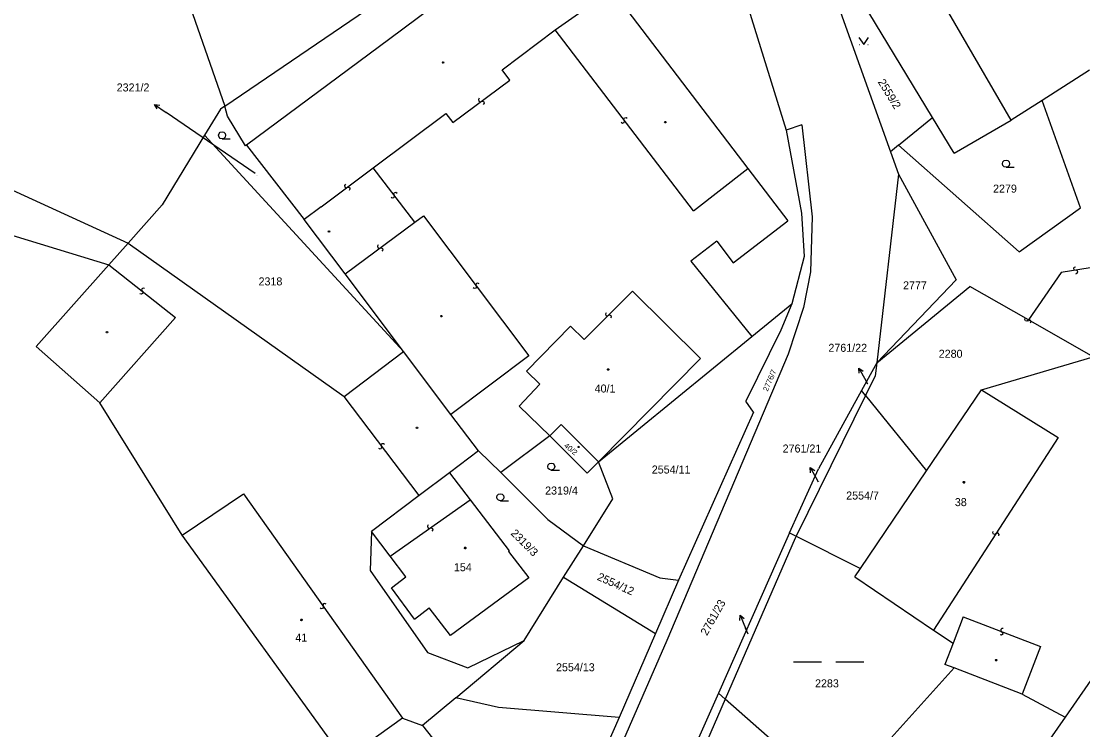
# Model space of a CAD drawing. Extents: x -747792 to -745414, y -1093712 to -1091463.
# Drawn here: x -746685.5 to -746572.8, y -1092966.2 to -1092891 of the extents above; entities that cross this region are included whole.
import ezdxf

# ---------------------------------------------------------------- set-up
doc = ezdxf.new("R2010")
doc.units = 0
for name, color, linetype in [('Pracovní_bod JDTM STC_VC', 7, 'Continuous'), ('Pracovní_bod JDTM STC_VC - výška', 7, 'Continuous'), ('Pracovní_bod JDTM STC_VC - číslo', 7, 'Continuous'), ('Pracovní_bod NN - výška', 7, 'Continuous'), ('Pracovní_bod polohopisu', 7, 'Continuous'), ('Pracovní_bod polohopisu - výška', 7, 'Continuous')]:
    doc.layers.add(name, color=color, linetype=linetype)

msp = doc.modelspace()

# ---------------------------------------------------------------- linework, layer by layer
at = {"layer": 'Pracovní_bod JDTM STC_VC - výška'}
for points in [[(-746640.68, -1092895.33), (-746640.63, -1092895.41), (-746640.68, -1092895.48), (-746640.76, -1092895.48), (-746640.81, -1092895.41), (-746640.76, -1092895.33)], [(-746617.05, -1092901.66), (-746617.01, -1092901.73), (-746617.05, -1092901.8), (-746617.15, -1092901.8), (-746617.19, -1092901.73), (-746617.15, -1092901.66)], [(-746652.79, -1092913.25), (-746652.75, -1092913.32), (-746652.79, -1092913.4), (-746652.89, -1092913.4), (-746652.93, -1092913.32), (-746652.89, -1092913.25)], [(-746640.84, -1092922.25), (-746640.8, -1092922.32), (-746640.84, -1092922.4), (-746640.94, -1092922.4), (-746640.98, -1092922.32), (-746640.94, -1092922.25)], [(-746676.38, -1092923.97), (-746676.33, -1092924.04), (-746676.38, -1092924.11), (-746676.47, -1092924.11), (-746676.51, -1092924.04), (-746676.47, -1092923.97)], [(-746623.19, -1092927.91), (-746623.14, -1092927.92), (-746623.11, -1092927.96), (-746623.1, -1092927.99), (-746623.11, -1092928.04), (-746623.16, -1092928.07), (-746623.19, -1092928.07), (-746623.23, -1092928.06), (-746623.26, -1092928.03), (-746623.27, -1092927.99), (-746623.26, -1092927.94), (-746623.22, -1092927.91)], [(-746643.45, -1092934.1), (-746643.4, -1092934.18), (-746643.45, -1092934.26), (-746643.53, -1092934.26), (-746643.58, -1092934.18), (-746643.53, -1092934.1)], [(-746626.33, -1092936.14), (-746626.3, -1092936.15), (-746626.28, -1092936.18), (-746626.27, -1092936.2), (-746626.28, -1092936.23), (-746626.31, -1092936.25), (-746626.33, -1092936.26), (-746626.36, -1092936.25), (-746626.38, -1092936.23), (-746626.39, -1092936.2), (-746626.38, -1092936.17), (-746626.35, -1092936.15)], [(-746585.4, -1092939.88), (-746585.35, -1092939.89), (-746585.33, -1092939.93), (-746585.32, -1092939.96), (-746585.33, -1092940.01), (-746585.36, -1092940.04), (-746585.4, -1092940.04), (-746585.45, -1092940.03), (-746585.48, -1092940), (-746585.49, -1092939.96), (-746585.48, -1092939.92), (-746585.44, -1092939.88)], [(-746638.38, -1092946.84), (-746638.33, -1092946.85), (-746638.3, -1092946.9), (-746638.29, -1092946.93), (-746638.3, -1092946.98), (-746638.34, -1092947.01), (-746638.38, -1092947.02), (-746638.43, -1092947), (-746638.46, -1092946.97), (-746638.47, -1092946.93), (-746638.46, -1092946.88), (-746638.42, -1092946.85)], [(-746655.77, -1092954.48), (-746655.72, -1092954.49), (-746655.7, -1092954.53), (-746655.69, -1092954.56), (-746655.7, -1092954.6), (-746655.74, -1092954.64), (-746655.77, -1092954.65), (-746655.82, -1092954.63), (-746655.84, -1092954.6), (-746655.85, -1092954.56), (-746655.84, -1092954.52), (-746655.8, -1092954.48)], [(-746581.93, -1092958.78), (-746581.88, -1092958.85), (-746581.93, -1092958.93), (-746582.01, -1092958.93), (-746582.06, -1092958.85), (-746582.01, -1092958.78)]]:
    msp.add_lwpolyline(points, close=True, dxfattribs=at)
at = {"layer": 'Pracovní_bod JDTM STC_VC - číslo'}
for points in [[(-746596.54, -1092892.73), (-746596.04, -1092893.48), (-746595.54, -1092892.73)], [(-746596.52, -1092893.48), (-746596.47, -1092893.48)], [(-746595.61, -1092893.48), (-746595.57, -1092893.48)], [(-746664.2, -1092903.5), (-746664.39, -1092903.45), (-746664.52, -1092903.31), (-746664.58, -1092903.12), (-746664.52, -1092902.94), (-746664.39, -1092902.8), (-746664.2, -1092902.75), (-746664.01, -1092902.8), (-746663.88, -1092902.94), (-746663.83, -1092903.12), (-746663.88, -1092903.31), (-746664.01, -1092903.45), (-746664.2, -1092903.5), (-746663.33, -1092903.5)], [(-746580.92, -1092906.51), (-746581.11, -1092906.46), (-746581.25, -1092906.32), (-746581.3, -1092906.14), (-746581.25, -1092905.95), (-746581.11, -1092905.81), (-746580.92, -1092905.76), (-746580.73, -1092905.81), (-746580.59, -1092905.95), (-746580.55, -1092906.14), (-746580.59, -1092906.32), (-746580.73, -1092906.46), (-746580.92, -1092906.51), (-746580.05, -1092906.51)], [(-746629.23, -1092938.67), (-746629.42, -1092938.62), (-746629.55, -1092938.48), (-746629.6, -1092938.29), (-746629.55, -1092938.11), (-746629.42, -1092937.97), (-746629.23, -1092937.92), (-746629.04, -1092937.97), (-746628.91, -1092938.11), (-746628.85, -1092938.29), (-746628.91, -1092938.48), (-746629.04, -1092938.62), (-746629.23, -1092938.67), (-746628.35, -1092938.67)], [(-746634.63, -1092941.92), (-746634.82, -1092941.87), (-746634.96, -1092941.73), (-746635.01, -1092941.54), (-746634.96, -1092941.36), (-746634.82, -1092941.22), (-746634.63, -1092941.17), (-746634.44, -1092941.22), (-746634.3, -1092941.36), (-746634.26, -1092941.54), (-746634.3, -1092941.73), (-746634.44, -1092941.87), (-746634.63, -1092941.92), (-746633.76, -1092941.92)], [(-746603.51, -1092959.03), (-746600.51, -1092959.03)], [(-746599.01, -1092959.03), (-746596.01, -1092959.03)]]:
    msp.add_lwpolyline(points, dxfattribs=at)
at = {"layer": 'Pracovní_bod NN - výška'}
for points in [[(-746663.9, -1092900.02), (-746615.33, -1092867)], [(-746615.33, -1092867), (-746604.26, -1092902.58)], [(-746673.9, -1092871.4), (-746663.9, -1092900.02)], [(-746605.01, -1092871.84), (-746593.18, -1092904.87)], [(-746628.81, -1092879.8), (-746646.38, -1092892.9)], [(-746588.72, -1092901.23), (-746599.54, -1092883.4)], [(-746622.81, -1092887.67), (-746608.35, -1092906.65)], [(-746646.38, -1092892.9), (-746661.6, -1092904.16)], [(-746572.05, -1092896.22), (-746577.08, -1092899.42)], [(-746577.08, -1092899.42), (-746580.37, -1092901.51)], [(-746573.02, -1092910.82), (-746577.08, -1092899.42)], [(-746664.37, -1092900.34), (-746666.05, -1092903.11)], [(-746663.9, -1092900.02), (-746664.37, -1092900.34)], [(-746663.62, -1092901.08), (-746663.9, -1092900.02)], [(-746661.72, -1092904.25), (-746663.62, -1092901.08)], [(-746602.61, -1092902.03), (-746604.26, -1092902.58)], [(-746602.61, -1092902.03), (-746601.52, -1092911.78)], [(-746592.33, -1092904.17), (-746588.72, -1092901.23)], [(-746586.43, -1092905.01), (-746588.72, -1092901.23)], [(-746586.43, -1092905.01), (-746580.37, -1092901.51)], [(-746699.3, -1092903.07), (-746674.17, -1092914.57)], [(-746666.05, -1092903.11), (-746670.57, -1092910.51)], [(-746666.05, -1092903.11), (-746644.92, -1092926.07)], [(-746604.26, -1092902.58), (-746602.64, -1092911.38)], [(-746661.6, -1092904.16), (-746661.72, -1092904.25)], [(-746661.6, -1092904.16), (-746655.46, -1092912.05)], [(-746592.33, -1092904.17), (-746593.18, -1092904.87)], [(-746592.33, -1092904.17), (-746579.52, -1092915.49)], [(-746593.18, -1092904.87), (-746592.33, -1092907.24)], [(-746608.35, -1092906.65), (-746604.1, -1092912.22)], [(-746592.33, -1092907.24), (-746594.65, -1092927.27)], [(-746592.33, -1092907.24), (-746586.23, -1092918.47)], [(-746701.96, -1092909.01), (-746676.22, -1092916.88)], [(-746674.17, -1092914.57), (-746670.57, -1092910.51)], [(-746579.52, -1092915.49), (-746573.02, -1092910.82)], [(-746651.11, -1092917.83), (-746655.46, -1092912.05)], [(-746602.64, -1092911.38), (-746602.35, -1092915.98)], [(-746601.52, -1092911.78), (-746601.7, -1092917.63)], [(-746609.89, -1092916.66), (-746604.1, -1092912.22)], [(-746611.65, -1092914.38), (-746614.4, -1092916.48)], [(-746611.65, -1092914.38), (-746609.89, -1092916.66)], [(-746676.22, -1092916.88), (-746674.17, -1092914.57)], [(-746674.17, -1092914.57), (-746651.24, -1092930.86)], [(-746614.4, -1092916.48), (-746607.93, -1092924.48)], [(-746602.35, -1092915.98), (-746603.67, -1092921.01)], [(-746683.93, -1092925.56), (-746676.22, -1092916.88)], [(-746644.92, -1092926.07), (-746651.11, -1092917.83)], [(-746601.7, -1092917.63), (-746602.43, -1092921.4)], [(-746586.23, -1092918.47), (-746594.65, -1092927.27)], [(-746594.65, -1092927.27), (-746584.78, -1092919.16)], [(-746578.55, -1092922.72), (-746584.78, -1092919.16)], [(-746607.93, -1092924.48), (-746603.67, -1092921.01)], [(-746603.67, -1092921.01), (-746604.83, -1092923.82)], [(-746602.43, -1092921.4), (-746604.07, -1092926.36)], [(-746571.67, -1092926.65), (-746578.55, -1092922.72)], [(-746624.21, -1092937.78), (-746607.93, -1092924.48)], [(-746604.83, -1092923.82), (-746608.55, -1092931.35)], [(-746677.19, -1092931.52), (-746683.93, -1092925.56)], [(-746651.24, -1092930.86), (-746644.92, -1092926.07)], [(-746639.88, -1092932.75), (-746644.92, -1092926.07)], [(-746604.07, -1092926.36), (-746616.96, -1092956.74)], [(-746583.54, -1092930.14), (-746571.67, -1092926.65)], [(-746594.65, -1092927.27), (-746596.27, -1092930.23)], [(-746594.65, -1092927.27), (-746594.81, -1092928.65)], [(-746594.81, -1092928.65), (-746595.86, -1092930.73)], [(-746596.27, -1092930.23), (-746600.83, -1092938.54)], [(-746595.86, -1092930.73), (-746596.27, -1092930.23)], [(-746589.37, -1092938.75), (-746583.54, -1092930.14)], [(-746607.76, -1092932.52), (-746608.55, -1092931.35)], [(-746595.86, -1092930.73), (-746603.22, -1092945.67)], [(-746595.86, -1092930.73), (-746589.37, -1092938.75)], [(-746668.44, -1092945.56), (-746677.19, -1092931.52)], [(-746636.94, -1092936.61), (-746639.88, -1092932.75)], [(-746607.76, -1092932.52), (-746615.71, -1092950.34)], [(-746628.18, -1092933.84), (-746629.37, -1092935.04)], [(-746628.18, -1092933.84), (-746624.21, -1092937.78)], [(-746629.37, -1092935.04), (-746634.6, -1092938.92)], [(-746625.41, -1092938.99), (-746629.37, -1092935.04)], [(-746636.94, -1092936.61), (-746640.05, -1092938.96)], [(-746634.6, -1092938.92), (-746636.94, -1092936.61)], [(-746624.21, -1092937.78), (-746625.41, -1092938.99)], [(-746622.69, -1092941.7), (-746624.21, -1092937.78)], [(-746640.05, -1092938.96), (-746643.27, -1092941.38)], [(-746640.05, -1092938.96), (-746637.85, -1092941.82)], [(-746634.6, -1092938.92), (-746629.59, -1092943.92)], [(-746603.91, -1092945.33), (-746600.83, -1092938.54)], [(-746596.38, -1092949.1), (-746589.37, -1092938.75)], [(-746643.27, -1092941.38), (-746648.32, -1092945.19)], [(-746637.85, -1092941.82), (-746633.7, -1092947.23)], [(-746625.82, -1092946.7), (-746622.69, -1092941.7)], [(-746629.59, -1092943.92), (-746625.82, -1092946.7)], [(-746651.2, -1092969.42), (-746668.44, -1092945.56)], [(-746648.32, -1092945.19), (-746648.46, -1092949.31)], [(-746646.34, -1092947.81), (-746648.32, -1092945.19)], [(-746603.33, -1092945.89), (-746610.76, -1092962.98)], [(-746603.91, -1092945.33), (-746605.21, -1092948.19)], [(-746603.91, -1092945.33), (-746603.22, -1092945.67)], [(-746603.22, -1092945.67), (-746603.33, -1092945.89)], [(-746603.22, -1092945.67), (-746596.38, -1092949.1)], [(-746627.92, -1092950.04), (-746625.82, -1092946.7)], [(-746625.82, -1092946.7), (-746617.69, -1092950.12)], [(-746644.68, -1092950.01), (-746646.34, -1092947.81)], [(-746633.7, -1092947.23), (-746633.78, -1092947.29)], [(-746633.78, -1092947.29), (-746631.6, -1092950.11)], [(-746605.21, -1092948.19), (-746611.48, -1092962.35)], [(-746648.46, -1092949.31), (-746642.39, -1092958.03)], [(-746596.98, -1092949.99), (-746596.38, -1092949.1)], [(-746646.2, -1092951.15), (-746644.68, -1092950.01)], [(-746631.6, -1092950.11), (-746639.92, -1092956.23)], [(-746632.12, -1092956.74), (-746627.92, -1092950.04)], [(-746627.92, -1092950.04), (-746618.14, -1092956.01)], [(-746615.71, -1092950.34), (-746618.14, -1092956.01)], [(-746617.69, -1092950.12), (-746615.71, -1092950.34)], [(-746596.98, -1092949.99), (-746588.62, -1092955.65)], [(-746643.74, -1092954.5), (-746646.2, -1092951.15)], [(-746643.74, -1092954.5), (-746642.19, -1092953.3)], [(-746639.92, -1092956.23), (-746642.19, -1092953.3)], [(-746618.14, -1092956.01), (-746622.01, -1092964.92)], [(-746588.62, -1092955.65), (-746586.55, -1092957.05)], [(-746639.38, -1092962.83), (-746632.12, -1092956.74)], [(-746638.1, -1092959.64), (-746632.12, -1092956.74)], [(-746616.96, -1092956.74), (-746628.34, -1092982.88)], [(-746586.55, -1092957.05), (-746587.41, -1092959.29)], [(-746642.39, -1092958.03), (-746638.1, -1092959.64)], [(-746586.42, -1092959.67), (-746587.41, -1092959.29)], [(-746586.42, -1092959.67), (-746598.85, -1092973.44)], [(-746579.19, -1092962.44), (-746586.42, -1092959.67)], [(-746639.38, -1092962.83), (-746642.89, -1092965.77)], [(-746634.82, -1092963.86), (-746639.38, -1092962.83)], [(-746611.48, -1092962.35), (-746618.21, -1092977.55)], [(-746610.76, -1092962.98), (-746611.48, -1092962.35)], [(-746579.19, -1092962.44), (-746574.63, -1092964.9)], [(-746622.01, -1092964.92), (-746634.82, -1092963.86)], [(-746610.76, -1092962.98), (-746619.05, -1092982.07)], [(-746598.85, -1092973.44), (-746610.76, -1092962.98)], [(-746645.02, -1092965.01), (-746651.2, -1092969.42)], [(-746645.02, -1092965.01), (-746642.89, -1092965.77)], [(-746622.01, -1092964.92), (-746629.27, -1092981.35)], [(-746574.63, -1092964.9), (-746577.88, -1092969.58)], [(-746642.89, -1092965.77), (-746641.85, -1092967.12)]]:
    msp.add_lwpolyline(points, dxfattribs=at)
at = {"layer": 'Pracovní_bod polohopisu'}
for points in [[(-746580.37, -1092901.51), (-746594.52, -1092877.17)], [(-746628.83, -1092891.92), (-746622.81, -1092887.67)], [(-746634.43, -1092896.18), (-746628.83, -1092891.92)], [(-746614.13, -1092911.14), (-746628.83, -1092891.92)], [(-746633.64, -1092897.26), (-746634.43, -1092896.18)], [(-746639.69, -1092901.78), (-746633.64, -1092897.26)], [(-746636.87, -1092899.2), (-746636.96, -1092899.33), (-746636.91, -1092899.49), (-746636.78, -1092899.56), (-746636.53, -1092899.49), (-746636.4, -1092899.56), (-746636.37, -1092899.72), (-746636.46, -1092899.84)], [(-746648.14, -1092906.59), (-746640.42, -1092900.82)], [(-746640.42, -1092900.82), (-746639.69, -1092901.78)], [(-746621.79, -1092901.74), (-746621.66, -1092901.83), (-746621.5, -1092901.78), (-746621.44, -1092901.64), (-746621.52, -1092901.4), (-746621.44, -1092901.27), (-746621.28, -1092901.24), (-746621.17, -1092901.32)], [(-746653.66, -1092910.71), (-746648.14, -1092906.59)], [(-746643.71, -1092912.35), (-746648.14, -1092906.59)], [(-746614.13, -1092911.14), (-746608.35, -1092906.65)], [(-746651.1, -1092908.33), (-746651.19, -1092908.46), (-746651.15, -1092908.62), (-746651.01, -1092908.69), (-746650.77, -1092908.62), (-746650.64, -1092908.69), (-746650.61, -1092908.85), (-746650.7, -1092908.97)], [(-746646.24, -1092909.68), (-746646.11, -1092909.77), (-746645.95, -1092909.72), (-746645.88, -1092909.58), (-746645.96, -1092909.34), (-746645.89, -1092909.21), (-746645.73, -1092909.17), (-746645.61, -1092909.26)], [(-746653.66, -1092910.71), (-746655.46, -1092912.05)], [(-746643.71, -1092912.35), (-746642.79, -1092911.67)], [(-746642.79, -1092911.67), (-746631.61, -1092926.54)], [(-746651.11, -1092917.83), (-746643.71, -1092912.35)], [(-746647.61, -1092914.77), (-746647.7, -1092914.9), (-746647.66, -1092915.06), (-746647.52, -1092915.13), (-746647.28, -1092915.06), (-746647.15, -1092915.13), (-746647.12, -1092915.29), (-746647.21, -1092915.41)], [(-746676.22, -1092916.88), (-746669.15, -1092922.46)], [(-746575.05, -1092917.7), (-746578.55, -1092922.72)], [(-746571.99, -1092917.21), (-746575.05, -1092917.7)], [(-746573.49, -1092917.83), (-746573.35, -1092917.76), (-746573.31, -1092917.59), (-746573.4, -1092917.47), (-746573.65, -1092917.43), (-746573.73, -1092917.3), (-746573.69, -1092917.14), (-746573.55, -1092917.08)], [(-746636.89, -1092918.9), (-746637.02, -1092918.81), (-746637.18, -1092918.85), (-746637.24, -1092918.99), (-746637.16, -1092919.23), (-746637.24, -1092919.37), (-746637.4, -1092919.4), (-746637.51, -1092919.31)], [(-746672.43, -1092919.39), (-746672.58, -1092919.34), (-746672.72, -1092919.42), (-746672.75, -1092919.57), (-746672.62, -1092919.79), (-746672.66, -1092919.93), (-746672.8, -1092920), (-746672.94, -1092919.95)], [(-746625.72, -1092924.82), (-746620.61, -1092919.66)], [(-746620.61, -1092919.66), (-746613.36, -1092926.83)], [(-746623.41, -1092921.96), (-746623.48, -1092922.1), (-746623.42, -1092922.25), (-746623.27, -1092922.3), (-746623.04, -1092922.19), (-746622.9, -1092922.24), (-746622.85, -1092922.39), (-746622.92, -1092922.52)], [(-746669.15, -1092922.46), (-746677.19, -1092931.52)], [(-746631.86, -1092928.17), (-746627.2, -1092923.39)], [(-746627.2, -1092923.39), (-746625.72, -1092924.82)], [(-746578.31, -1092923.03), (-746578.26, -1092922.88), (-746578.35, -1092922.74), (-746578.5, -1092922.72), (-746578.71, -1092922.86), (-746578.86, -1092922.83), (-746578.94, -1092922.69), (-746578.89, -1092922.55)], [(-746578.55, -1092922.72), (-746578.65, -1092922.86)], [(-746631.61, -1092926.54), (-746639.88, -1092932.75)], [(-746613.36, -1092926.83), (-746624.21, -1092937.78)], [(-746630.44, -1092929.55), (-746631.86, -1092928.17)], [(-746630.44, -1092929.55), (-746632.64, -1092931.87)], [(-746583.54, -1092930.14), (-746575.37, -1092935.2)], [(-746643.27, -1092941.38), (-746651.24, -1092930.86)], [(-746629.37, -1092935.04), (-746632.64, -1092931.87)], [(-746647.57, -1092936.33), (-746647.44, -1092936.42), (-746647.28, -1092936.37), (-746647.21, -1092936.23), (-746647.29, -1092935.99), (-746647.22, -1092935.86), (-746647.06, -1092935.83), (-746646.94, -1092935.91)], [(-746575.37, -1092935.2), (-746588.62, -1092955.65)], [(-746668.44, -1092945.56), (-746661.91, -1092941.18)], [(-746661.91, -1092941.18), (-746645.02, -1092965.01)], [(-746646.34, -1092947.81), (-746637.85, -1092941.82)], [(-746559.86, -1092943.62), (-746574.63, -1092964.9)], [(-746642.29, -1092944.49), (-746642.38, -1092944.62), (-746642.34, -1092944.78), (-746642.21, -1092944.85), (-746641.96, -1092944.78), (-746641.83, -1092944.86), (-746641.81, -1092945.02), (-746641.9, -1092945.14)], [(-746581.69, -1092945.65), (-746581.65, -1092945.5), (-746581.75, -1092945.36), (-746581.9, -1092945.35), (-746582.1, -1092945.5), (-746582.26, -1092945.48), (-746582.34, -1092945.34), (-746582.3, -1092945.2)], [(-746653.14, -1092952.9), (-746653.27, -1092952.81), (-746653.43, -1092952.85), (-746653.5, -1092952.98), (-746653.43, -1092953.23), (-746653.51, -1092953.36), (-746653.67, -1092953.38), (-746653.79, -1092953.29)], [(-746585.48, -1092954.25), (-746586.55, -1092957.05)], [(-746585.48, -1092954.25), (-746577.27, -1092957.4)], [(-746581.22, -1092955.48), (-746581.38, -1092955.48), (-746581.49, -1092955.6), (-746581.47, -1092955.75), (-746581.28, -1092955.92), (-746581.27, -1092956.07), (-746581.39, -1092956.18), (-746581.53, -1092956.17)], [(-746577.27, -1092957.4), (-746579.19, -1092962.44)]]:
    msp.add_lwpolyline(points, dxfattribs=at)
at = {"layer": 'Pracovní_bod polohopisu - výška'}
for points in [[(-746671.37, -1092899.84), (-746670.13, -1092900.69)], [(-746671.1, -1092900.33), (-746671.37, -1092899.84), (-746670.81, -1092899.92)], [(-746660.68, -1092907.18), (-746670.13, -1092900.69)], [(-746596.56, -1092927.83), (-746595.82, -1092929.14)], [(-746596.53, -1092928.39), (-746596.56, -1092927.83), (-746596.09, -1092928.15)], [(-746595.6, -1092929.54), (-746595.82, -1092929.14)], [(-746601.71, -1092938.39), (-746600.97, -1092939.7)], [(-746601.68, -1092938.95), (-746601.71, -1092938.39), (-746601.24, -1092938.71)], [(-746600.84, -1092939.93), (-746600.97, -1092939.7)], [(-746609.19, -1092954.62), (-746609.15, -1092954.06), (-746608.73, -1092954.43)], [(-746609.15, -1092954.06), (-746608.58, -1092955.45)], [(-746608.32, -1092956.08), (-746608.58, -1092955.45)]]:
    msp.add_lwpolyline(points, dxfattribs=at)

# ---------------------------------------------------------------- texts
at = {"layer": 'Pracovní_bod JDTM STC_VC'}
for s, height, rotation, p in [('2559/2', 0.85, 301.605, (-746594.57, -1092897.47)), ('2776/7', 0.57, 66.9788, (-746606.24, -1092930.36)), ('2761/22', 0.05, 56.3218, (-746595.65, -1092929.67)), ('40/2', 0.57, 321.1428, (-746627.93, -1092936.17)), ('2319/3', 0.85, 315.0122, (-746633.6, -1092945.44)), ('2554/12', 0.85, 335.6387, (-746624.42, -1092950.29))]:
    msp.add_text(s, height=height, rotation=rotation, dxfattribs=at).set_placement(p)
for s, height, p in [('2321/2', 0.05, (-746660.67, -1092907.4)), ('2279', 0.85, (-746582.3, -1092909.21)), ('2318', 0.85, (-746660.32, -1092919.06)), ('2777', 0.85, (-746591.86, -1092919.48)), ('2280', 0.85, (-746588.07, -1092926.74)), ('40/1', 0.85, (-746624.62, -1092930.43)), ('2554/11', 0.85, (-746618.55, -1092939.03)), ('2319/4', 0.85, (-746629.88, -1092941.26)), ('2761/21', 0.05, (-746600.96, -1092939.93)), ('2554/7', 0.85, (-746597.9, -1092941.79)), ('38', 0.85, (-746586.36, -1092942.49)), ('154', 0.85, (-746639.57, -1092949.4)), ('41', 0.85, (-746656.42, -1092956.88)), ('2761/23', 0.05, (-746608.46, -1092956.08)), ('2554/13', 0.85, (-746628.72, -1092960.02)), ('2283', 0.85, (-746601.21, -1092961.73))]:
    msp.add_text(s, height=height, dxfattribs=at).set_placement(p)
at = {"layer": 'Pracovní_bod polohopisu - výška'}
for s, p in [('2321/2', (-746675.39, -1092898.47)), ('2761/22', (-746599.79, -1092926.11)), ('2761/21', (-746604.65, -1092936.8))]:
    msp.add_text(s, height=0.85, dxfattribs=at).set_placement(p)
msp.add_text('2761/23', height=0.85, rotation=60.5616, dxfattribs=at).set_placement((-746612.69, -1092956.3))

doc.saveas('drawing.dxf')
